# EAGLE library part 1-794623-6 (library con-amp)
MICRO MATE N LOK Dual Row, grid 1.5 mm Source: http://catalog.tycoelectronics.com .. ENG_CD_794623_F.pdf
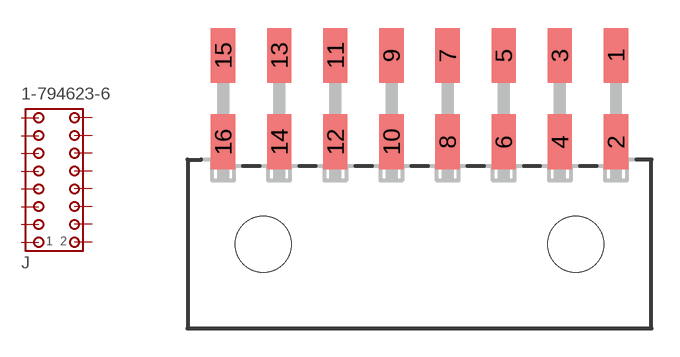
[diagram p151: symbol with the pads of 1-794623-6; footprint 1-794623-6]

Designator prefix J

## 1-794623-6 (MF: TYCO ELECTRONICS; MPN: 1-794623-6; OC_FARNELL: unknown; OC_NEWARK: 10H3685)  [1-794623-6]
1  1  pas
2  2  pas
3  3  pas
4  4  pas
5  5  pas
6  6  pas
7  7  pas
8  8  pas
9  9  pas
10  10  pas
11  11  pas
12  12  pas
13  13  pas
14  14  pas
15  15  pas
16  16  pas

## Footprint 1-794623-6 (pad centres in mm)
MICRO MATE N LOK Dual Row, grid 1.5 mm Source: http://catalog.tycoelectronics.com .. ENG_CD_794623_F.pdf
smd 1.3 x 2.92: 1 10.5,10.1; 2 10.5,5.48; 3 7.5,10.1; 4 7.5,5.48; 5 4.5,10.1; 6 4.5,5.48; 7 1.5,10.1; 8 1.5,5.48; 9 -1.5,10.1; 10 -1.5,5.48; 11 -4.5,10.1; 12 -4.5,5.48; 13 -7.5,10.1; 14 -7.5,5.48; 15 -10.5,10.1; 16 -10.5,5.48
hole 3 at -8.35,0
hole 3 at 8.35,0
